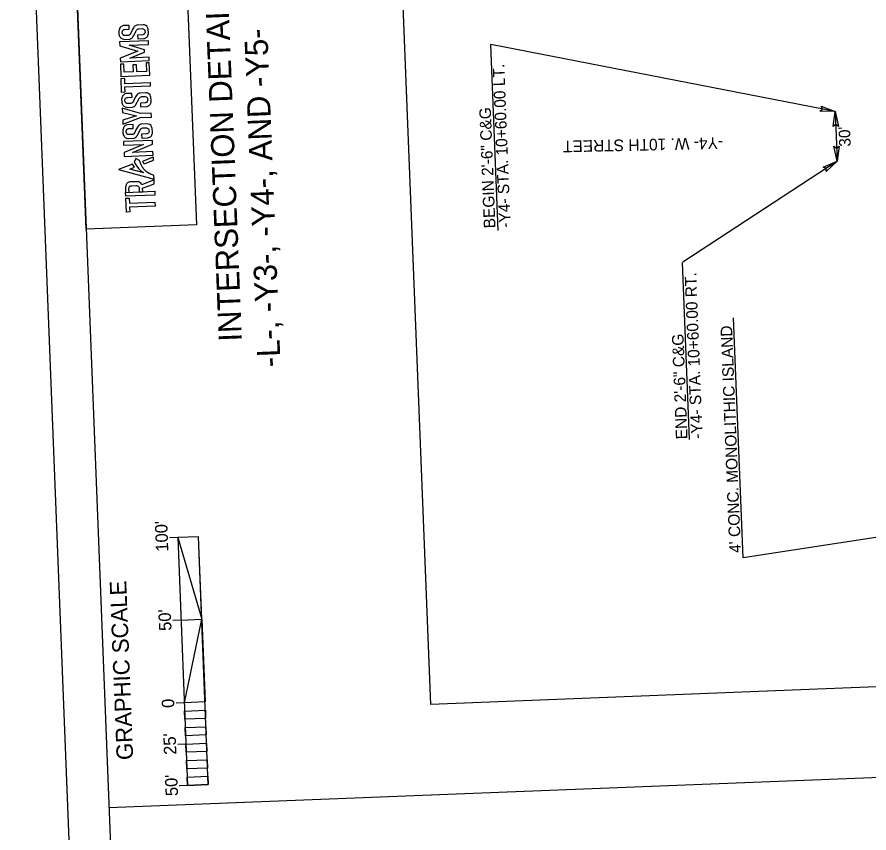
# Model space of a CAD drawing. Extents: x 1627847 to 1629013, y 761524 to 763498.
# Drawn here: x 1627847 to 1628362, y 762434 to 762927 of the extents above; entities that cross this region are included whole.
import ezdxf

# ---------------------------------------------------------------- set-up
doc = ezdxf.new("R2010")
doc.units = 0
for name, color, linetype in [('Old_Level_58', 7, 'Continuous'), ('Prop Dimension', 7, 'Continuous'), ('Prop Dimension Text', 7, 'Continuous'), ('Prop DSN Text', 7, 'Continuous'), ('Prop Terminator CELL', 7, 'Continuous'), ('Sheet Clip Boundary CELL', 7, 'Continuous'), ('Sheet Data Field CELL', 7, 'Continuous'), ('Sheet Plan And Profile CELL', 7, 'Continuous'), ('Sheet Plot Border Outside CELL', 7, 'Continuous'), ('Sheet Title CELL', 7, 'Continuous')]:
    doc.layers.add(name, color=color, linetype=linetype)

msp = doc.modelspace()

# ---------------------------------------------------------------- linework, layer by layer
at = {"layer": 'Old_Level_58'}
msp.add_lwpolyline([(1627888.94, 762798.77), (1627881.06, 762998.67), (1627947.7, 763001.3), (1627955.58, 762801.4)], close=True, dxfattribs=at)
at = {"layer": 'Prop Dimension'}
for p, q in [((1628137.91, 762798.04), (1628133.48, 762910.42)), ((1628341.64, 762869.95), (1628133.48, 762910.42)), ((1628341.64, 762869.95), (1628342.83, 762839.97)), ((1628342.83, 762839.97), (1628249.5, 762778.96)), ((1628253.68, 762671.78), (1628249.47, 762778.75)), ((1628285.96, 762600.1), (1628280.24, 762745.25)), ((1628457.54, 762626.57), (1628285.96, 762600.1)), ((1627902.73, 762449.14), (1628951.92, 762490.52))]:
    msp.add_line(p, q, dxfattribs=at)
for points in [[(1627915.05, 762919.72), (1627914.95, 762922.03), (1627911.48, 762921.89), (1627910.78, 762921.66), (1627910.2, 762921.36), (1627909.83, 762921.05), (1627909.49, 762920.66), (1627909.22, 762920.21), (1627909.07, 762919.78), (1627909.07, 762919.78), (1627908.89, 762919.31), (1627908.79, 762918.83), (1627908.72, 762918.5), (1627908.83, 762916.76), (1627908.94, 762916.23), (1627909.03, 762915.78), (1627909.29, 762915.33), (1627909.52, 762914.93), (1627909.82, 762914.55), (1627910.14, 762914.25), (1627910.52, 762914.02), (1627910.92, 762913.84), (1627911.63, 762913.62), (1627912.14, 762913.59), (1627915.31, 762913.71), (1627915.78, 762913.85), (1627916.27, 762914.09), (1627916.67, 762914.4), (1627916.96, 762914.71), (1627917.29, 762915.17), (1627917.62, 762915.64), (1627917.83, 762915.93), (1627918.04, 762916.42), (1627918.24, 762916.91), (1627918.48, 762917.31), (1627918.75, 762917.77), (1627918.99, 762918.3), (1627919.2, 762918.74), (1627919.49, 762919.19), (1627919.78, 762919.51), (1627920, 762919.77), (1627920.48, 762919.94), (1627920.77, 762920.04), (1627923.01, 762920.1), (1627923.5, 762919.96), (1627923.93, 762919.73), (1627924.23, 762919.41), (1627924.41, 762919.06), (1627924.49, 762918.73), (1627924.55, 762917.77), (1627924.47, 762917.44), (1627924.29, 762917.1), (1627924.11, 762916.77), (1627923.78, 762916.61), (1627923.45, 762916.46), (1627923.19, 762916.33), (1627920.08, 762916.17), (1627920.2, 762913.84), (1627923.91, 762914.03), (1627924.19, 762914.16), (1627925.04, 762914.46), (1627925.32, 762914.65), (1627925.63, 762914.91), (1627925.99, 762915.31), (1627926.17, 762915.62), (1627926.34, 762916.06), (1627926.4, 762916.22), (1627926.56, 762916.66), (1627926.59, 762917.2), (1627926.62, 762917.59), (1627926.48, 762919.73), (1627926.31, 762920.32), (1627925.91, 762921.13), (1627925.77, 762921.4), (1627924.95, 762921.99), (1627924.15, 762922.29), (1627923.44, 762922.42), (1627920.02, 762922.23), (1627919.55, 762922.21), (1627919.18, 762922.06), (1627918.83, 762921.85), (1627918.1, 762921.29), (1627917.57, 762920.56), (1627917.03, 762919.56), (1627916.61, 762918.8), (1627915.9, 762917.31), (1627915.37, 762916.53), (1627914.96, 762916.19), (1627914.68, 762916.1), (1627914.4, 762916.01), (1627911.97, 762915.96), (1627911.71, 762916.07), (1627911.45, 762916.19), (1627911.29, 762916.36), (1627911.09, 762916.58), (1627910.97, 762916.84), (1627910.85, 762917.09), (1627910.88, 762917.24), (1627910.8, 762917.25), (1627910.78, 762918.21), (1627910.88, 762918.49), (1627910.98, 762918.77), (1627911.08, 762919.05), (1627911.26, 762919.19), (1627911.54, 762919.39), (1627911.81, 762919.49), (1627912.08, 762919.59), (1627912.38, 762919.6)], [(1627920.27, 762906.39), (1627909.5, 762902.15), (1627909.7, 762899.94), (1627927.14, 762900.71), (1627927.05, 762902.82), (1627915.38, 762902.3), (1627924.23, 762905.92), (1627924.21, 762907.27), (1627914.97, 762909.98), (1627926.68, 762910.48), (1627926.58, 762912.76), (1627909.17, 762912.01), (1627909.27, 762909.71)], [(1627909.72, 762898.59), (1627910.02, 762891.21), (1627927.43, 762891.91), (1627927.13, 762899.38), (1627925.16, 762899.3), (1627925.36, 762894.26), (1627919.52, 762894.02), (1627919.35, 762898.23), (1627917.28, 762898.15), (1627917.45, 762893.9), (1627911.96, 762893.68), (1627911.75, 762898.69)], [(1627910.4, 762881.53), (1627910.05, 762889.99), (1627912.13, 762890.07), (1627912.25, 762886.97), (1627927.66, 762887.59), (1627927.76, 762885.24), (1627912.24, 762884.61), (1627912.36, 762881.64)], [(1627916.71, 762878.62), (1627916.61, 762880.93), (1627913.14, 762880.79), (1627912.44, 762880.56), (1627911.86, 762880.26), (1627911.48, 762879.95), (1627911.15, 762879.56), (1627910.88, 762879.11), (1627910.72, 762878.68), (1627910.72, 762878.68), (1627910.55, 762878.22), (1627910.45, 762877.73), (1627910.38, 762877.4), (1627910.49, 762875.66), (1627910.6, 762875.13), (1627910.69, 762874.68), (1627910.95, 762874.23), (1627911.18, 762873.83), (1627911.48, 762873.45), (1627911.8, 762873.15), (1627912.18, 762872.92), (1627912.58, 762872.74), (1627913.29, 762872.52), (1627913.8, 762872.49), (1627916.97, 762872.61), (1627917.44, 762872.75), (1627917.92, 762873), (1627918.32, 762873.3), (1627918.62, 762873.61), (1627918.95, 762874.07), (1627919.28, 762874.54), (1627919.49, 762874.83), (1627919.7, 762875.32), (1627919.9, 762875.81), (1627920.14, 762876.21), (1627920.41, 762876.67), (1627920.65, 762877.2), (1627920.85, 762877.65), (1627921.15, 762878.09), (1627921.44, 762878.41), (1627921.66, 762878.67), (1627922.14, 762878.84), (1627922.43, 762878.95), (1627924.67, 762879), (1627925.16, 762878.86), (1627925.59, 762878.63), (1627925.89, 762878.31), (1627926.07, 762877.96), (1627926.15, 762877.63), (1627926.21, 762876.67), (1627926.13, 762876.34), (1627925.95, 762876), (1627925.77, 762875.67), (1627925.44, 762875.51), (1627925.11, 762875.36), (1627924.85, 762875.23), (1627921.74, 762875.08), (1627921.86, 762872.74), (1627925.57, 762872.93), (1627925.84, 762873.06), (1627926.69, 762873.36), (1627926.98, 762873.55), (1627927.29, 762873.81), (1627927.65, 762874.21), (1627927.83, 762874.52), (1627927.99, 762874.96), (1627928.05, 762875.12), (1627928.22, 762875.56), (1627928.25, 762876.1), (1627928.27, 762876.49), (1627928.14, 762878.63), (1627927.97, 762879.22), (1627927.57, 762880.03), (1627927.43, 762880.3), (1627926.61, 762880.89), (1627925.81, 762881.19), (1627925.1, 762881.32), (1627921.68, 762881.13), (1627921.21, 762881.11), (1627920.84, 762880.96), (1627920.49, 762880.76), (1627919.76, 762880.19), (1627919.23, 762879.46), (1627918.69, 762878.46), (1627918.27, 762877.7), (1627917.56, 762876.21), (1627917.03, 762875.43), (1627916.62, 762875.09), (1627916.34, 762875), (1627916.06, 762874.91), (1627913.63, 762874.86), (1627913.37, 762874.97), (1627913.11, 762875.09), (1627912.95, 762875.26), (1627912.75, 762875.48), (1627912.63, 762875.74), (1627912.51, 762875.99), (1627912.54, 762876.14), (1627912.46, 762876.15), (1627912.44, 762877.11), (1627912.54, 762877.39), (1627912.64, 762877.67), (1627912.74, 762877.95), (1627912.92, 762878.09), (1627913.19, 762878.29), (1627913.47, 762878.39), (1627913.74, 762878.49), (1627914.04, 762878.5)], [(1627911.08, 762864.79), (1627911.18, 762862.25), (1627921.92, 762866.3), (1627928.45, 762866.59), (1627928.35, 762868.97), (1627921.86, 762868.68), (1627910.76, 762871.91), (1627910.93, 762869.42), (1627919.35, 762867.44)], [(1627917.47, 762859.76), (1627917.37, 762862.07), (1627913.9, 762861.93), (1627913.2, 762861.71), (1627912.62, 762861.4), (1627912.25, 762861.09), (1627911.91, 762860.71), (1627911.64, 762860.26), (1627911.49, 762859.82), (1627911.49, 762859.82), (1627911.31, 762859.36), (1627911.21, 762858.87), (1627911.14, 762858.55), (1627911.25, 762856.8), (1627911.36, 762856.28), (1627911.45, 762855.82), (1627911.71, 762855.37), (1627911.94, 762854.98), (1627912.24, 762854.59), (1627912.56, 762854.3), (1627912.94, 762854.07), (1627913.34, 762853.89), (1627914.05, 762853.66), (1627914.56, 762853.63), (1627917.73, 762853.76), (1627918.2, 762853.89), (1627918.69, 762854.14), (1627919.09, 762854.44), (1627919.38, 762854.75), (1627919.71, 762855.22), (1627920.04, 762855.68), (1627920.25, 762855.97), (1627920.46, 762856.47), (1627920.66, 762856.96), (1627920.9, 762857.36), (1627921.17, 762857.81), (1627921.41, 762858.35), (1627921.62, 762858.79), (1627921.91, 762859.23), (1627922.2, 762859.55), (1627922.42, 762859.81), (1627922.9, 762859.98), (1627923.19, 762860.09), (1627925.43, 762860.14), (1627925.92, 762860), (1627926.35, 762859.77), (1627926.65, 762859.46), (1627926.83, 762859.11), (1627926.91, 762858.77), (1627926.97, 762857.81), (1627926.89, 762857.48), (1627926.71, 762857.15), (1627926.53, 762856.81), (1627926.2, 762856.66), (1627925.87, 762856.5), (1627925.61, 762856.38), (1627922.5, 762856.22), (1627922.62, 762853.88), (1627926.33, 762854.07), (1627926.61, 762854.2), (1627927.46, 762854.51), (1627927.74, 762854.69), (1627928.05, 762854.96), (1627928.41, 762855.35), (1627928.59, 762855.66), (1627928.76, 762856.11), (1627928.82, 762856.27), (1627928.98, 762856.7), (1627929.01, 762857.24), (1627929.04, 762857.63), (1627928.9, 762859.77), (1627928.73, 762860.36), (1627928.33, 762861.17), (1627928.19, 762861.44), (1627927.37, 762862.03), (1627926.57, 762862.34), (1627925.86, 762862.46), (1627922.44, 762862.28), (1627921.97, 762862.25), (1627921.6, 762862.1), (1627921.25, 762861.9), (1627920.52, 762861.33), (1627919.99, 762860.6), (1627919.45, 762859.6), (1627919.03, 762858.84), (1627918.32, 762857.35), (1627917.79, 762856.57), (1627917.38, 762856.23), (1627917.1, 762856.14), (1627916.82, 762856.05), (1627914.39, 762856), (1627914.13, 762856.12), (1627913.87, 762856.23), (1627913.71, 762856.4), (1627913.51, 762856.63), (1627913.39, 762856.88), (1627913.27, 762857.13), (1627913.3, 762857.28), (1627913.22, 762857.29), (1627913.2, 762858.25), (1627913.3, 762858.53), (1627913.4, 762858.82), (1627913.5, 762859.1), (1627913.68, 762859.23), (1627913.96, 762859.43), (1627914.23, 762859.53), (1627914.5, 762859.64), (1627914.8, 762859.64)], [(1627911.96, 762842.83), (1627929.4, 762843.54), (1627929.31, 762845.77), (1627917.04, 762845.28), (1627929.16, 762850.21), (1627929.04, 762852.46), (1627911.55, 762851.75), (1627911.64, 762849.57), (1627923.62, 762850.06), (1627911.86, 762845.19)], [(1627908.45, 762834.92), (1627930.03, 762829.1), (1627929.93, 762831.32), (1627929.08, 762831.63), (1627927.9, 762832.16), (1627927.26, 762832.44), (1627926.71, 762832.8), (1627925.93, 762833.29), (1627925.45, 762833.6), (1627925.04, 762833.96), (1627924.63, 762834.33), (1627924.11, 762834.79), (1627923.83, 762835.19), (1627923.48, 762835.6), (1627923.14, 762836.14), (1627922.84, 762836.62), (1627922.22, 762837.81), (1627921.77, 762838.8), (1627921.15, 762840.42), (1627918.96, 762841.47), (1627918.1, 762839.26), (1627919.04, 762837.66), (1627920, 762836.32), (1627920.84, 762835.37), (1627921.28, 762834.86), (1627921.87, 762834.35), (1627922.46, 762833.84), (1627922.9, 762833.46), (1627923.56, 762833.11), (1627923.93, 762832.91), (1627915.45, 762835.21), (1627918.3, 762836.32), (1627916.97, 762838.17)], [(1627924.04, 762838.15), (1627923.2, 762840.04), (1627929.54, 762842.55), (1627929.55, 762840.45)], [(1627914.94, 762821.14), (1627914.84, 762823.53), (1627914.88, 762823.83), (1627915.02, 762824.24), (1627915.23, 762824.57), (1627915.49, 762824.81), (1627915.82, 762824.98), (1627916.07, 762825.11), (1627916.65, 762825.14), (1627919.14, 762825.24), (1627919.47, 762825.2), (1627919.92, 762825.13), (1627920.21, 762825.01), (1627920.48, 762824.82), (1627920.71, 762824.56), (1627920.87, 762824.14), (1627920.93, 762823.82), (1627920.99, 762823.49), (1627921.08, 762821.39), (1627923.18, 762821.48), (1627923.09, 762823.59), (1627930.15, 762826.24), (1627930.03, 762828.65), (1627922.6, 762825.7), (1627922.45, 762826.08), (1627922.03, 762826.6), (1627921.48, 762827.06), (1627920.84, 762827.39), (1627920.2, 762827.58), (1627920.01, 762827.56), (1627915.44, 762827.42), (1627914.71, 762827.18), (1627914.05, 762826.8), (1627913.59, 762826.37), (1627913.14, 762825.65), (1627912.94, 762824.96), (1627912.75, 762824.28), (1627912.76, 762823.87), (1627912.85, 762821.06)], [(1627912.94, 762818.74), (1627912.85, 762821.06), (1627930.4, 762821.76), (1627930.5, 762819.45)], [(1627913.32, 762809.13), (1627912.98, 762817.59), (1627915.05, 762817.67), (1627915.18, 762814.57), (1627930.58, 762815.19), (1627930.68, 762812.84), (1627915.17, 762812.21), (1627915.29, 762809.24)]]:
    msp.add_lwpolyline(points, close=True, dxfattribs=at)
at = {"layer": 'Prop Terminator CELL'}
for points in [[(1628333.1, 762873.19), (1628341.64, 762869.95), (1628332.45, 762870.11), (1628333.89, 762871.46)], [(1628340.45, 762860.9), (1628341.64, 762869.95), (1628343.6, 762860.97), (1628341.96, 762862.06)], [(1628344.02, 762849.03), (1628342.83, 762839.97), (1628340.87, 762848.95), (1628342.52, 762847.87)], [(1628334.45, 762836.35), (1628342.83, 762839.97), (1628336.13, 762833.68), (1628336.22, 762835.65)]]:
    msp.add_lwpolyline(points, close=True, dxfattribs=at)
at = {"layer": 'Sheet Clip Boundary CELL'}
msp.add_lwpolyline([(1628097.28, 762511.58), (1628072.8, 763132.43), (1628198.63, 763137.39), (1628215.93, 763082.79), (1628256.43, 763089.13), (1628269.19, 763140.18), (1628768.96, 763159.88), (1628793.44, 762539.03)], close=True, dxfattribs=at)
at = {"layer": 'Sheet Data Field CELL'}
for p, q in [((1627944.36, 762612.47), (1627939.36, 762612.27)), ((1627946.32, 762562.52), (1627941.34, 762562.32)), ((1627949.3, 762487.6), (1627944.3, 762487.4)), ((1627950.27, 762462.63), (1627945.29, 762462.43))]:
    msp.add_line(p, q, dxfattribs=at)
at = {"layer": 'Sheet Plan And Profile CELL'}
msp.add_lwpolyline([(1627873.18, 763198.56), (1627932.28, 761699.73), (1628981.47, 761741.1), (1628922.36, 763239.94)], close=True, dxfattribs=at)
at = {"layer": 'Sheet Plot Border Outside CELL'}
msp.add_lwpolyline([(1629013.34, 761567.22), (1628946.36, 763265.9), (1627847.21, 763222.56), (1627914.2, 761523.88)], close=True, dxfattribs=at)
at = {"layer": 'Sheet Title CELL'}
for p, q in [((1627944.36, 762612.45), (1627939.37, 762612.26)), ((1627956.86, 762612.95), (1627944.36, 762612.45)), ((1627944.36, 762612.45), (1627950.28, 762462.61)), ((1627962.77, 762463.11), (1627956.86, 762612.95)), ((1627946.34, 762562.51), (1627941.36, 762562.31)), ((1627946.34, 762562.51), (1627958.82, 762563)), ((1627948.32, 762512.56), (1627943.33, 762512.36)), ((1627948.9, 762497.58), (1627961.39, 762498.07)), ((1627949.31, 762487.59), (1627944.3, 762487.39)), ((1627950.28, 762462.61), (1627962.77, 762463.11)), ((1627950.28, 762462.61), (1627945.3, 762462.42)), ((1627945.3, 762462.42), (1627945.3, 762462.42)), ((1627950.28, 762462.61), (1627950.28, 762462.61))]:
    msp.add_line(p, q, dxfattribs=at)
for points in [[(1627944.36, 762612.45), (1627958.82, 762563), (1627956.86, 762612.95)], [(1627948.32, 762512.56), (1627958.82, 762563), (1627960.81, 762513.05)], [(1627948.71, 762502.57), (1627948.51, 762507.57), (1627961.01, 762508.06), (1627961.19, 762503.06)], [(1627949.11, 762492.58), (1627948.9, 762497.58), (1627961.39, 762498.07), (1627961.59, 762493.08)], [(1627949.51, 762482.59), (1627949.31, 762487.59), (1627961.78, 762488.08), (1627961.98, 762483.09)], [(1627949.89, 762472.6), (1627949.71, 762477.6), (1627962.19, 762478.09), (1627962.39, 762473.11)], [(1627950.28, 762462.61), (1627950.09, 762467.61), (1627962.57, 762468.1), (1627962.77, 762463.11)]]:
    msp.add_lwpolyline(points, close=True, dxfattribs=at)

# ---------------------------------------------------------------- texts
at = {"layer": 'Prop Dimension'}
for s, p in [('INTERSECTION DETAIL', (1627983.14, 762731.14)), ('-L-, -Y3-, -Y4-, AND -Y5-', (1628006.52, 762715.61))]:
    msp.add_text(s, height=14, rotation=92.2582, dxfattribs=at).set_placement(p)
at = {"layer": 'Prop Dimension Text'}
for s, rotation, p in [('-Y4- STA. 10+60.00 LT.', 92.2582, (1628145.55, 762799.86)), ('BEGIN 2\'-6" C&G', 92.2582, (1628136.38, 762799.5)), ("30'", 92.2723, (1628351.09, 762848.84)), ('-Y4- STA. 10+60.00 RT.', 92.2582, (1628261.61, 762672.31)), ('END 2\'-6" C&G', 92.2582, (1628252.44, 762671.95))]:
    msp.add_text(s, height=7, rotation=rotation, dxfattribs=at).set_placement(p)
at = {"layer": 'Prop DSN Text'}
for s, rotation, p in [('-Y4- W. 10TH STREET', 181.2524, (1628273.78, 762854.41)), ("4' CONC. MONOLITHIC ISLAND", 92.2582, (1628284.73, 762603.32))]:
    msp.add_text(s, height=7, rotation=rotation, dxfattribs=at).set_placement(p)
at = {"layer": 'Sheet Data Field CELL'}
for s, p in [("100'", (1627938.68, 762604.01)), ("50'", (1627940.59, 762556.13)), ("25'", (1627943.55, 762481.21)), ("50'", (1627944.53, 762456.23))]:
    msp.add_text(s, height=7.498, rotation=92.263, dxfattribs=at).set_placement(p)
at = {"layer": 'Sheet Title CELL'}
for s, height, p in [('GRAPHIC SCALE', 9.9967, (1627917.46, 762478.13)), ('0', 7.5, (1627942.29, 762509.57))]:
    msp.add_text(s, height=height, rotation=92.263, dxfattribs=at).set_placement(p)

doc.saveas('drawing.dxf')
